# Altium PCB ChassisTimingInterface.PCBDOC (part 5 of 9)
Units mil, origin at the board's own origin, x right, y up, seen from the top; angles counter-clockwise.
Board outline 7007.87 x 4368.85 mil, 10 copper layers (Top Layer, Int1 (GND), Int2 (Sign), Int3 (Sign), Int4 (PWR), Int5 (GND), Int6 (Sign), Int7 (Sign), Int8 (GND), Bottom Layer), stack 54.89 mil thick; 537 components, 525 nets, 2288 pads, 1306 vias.
Unrouted connection lines stored in the file: 373.
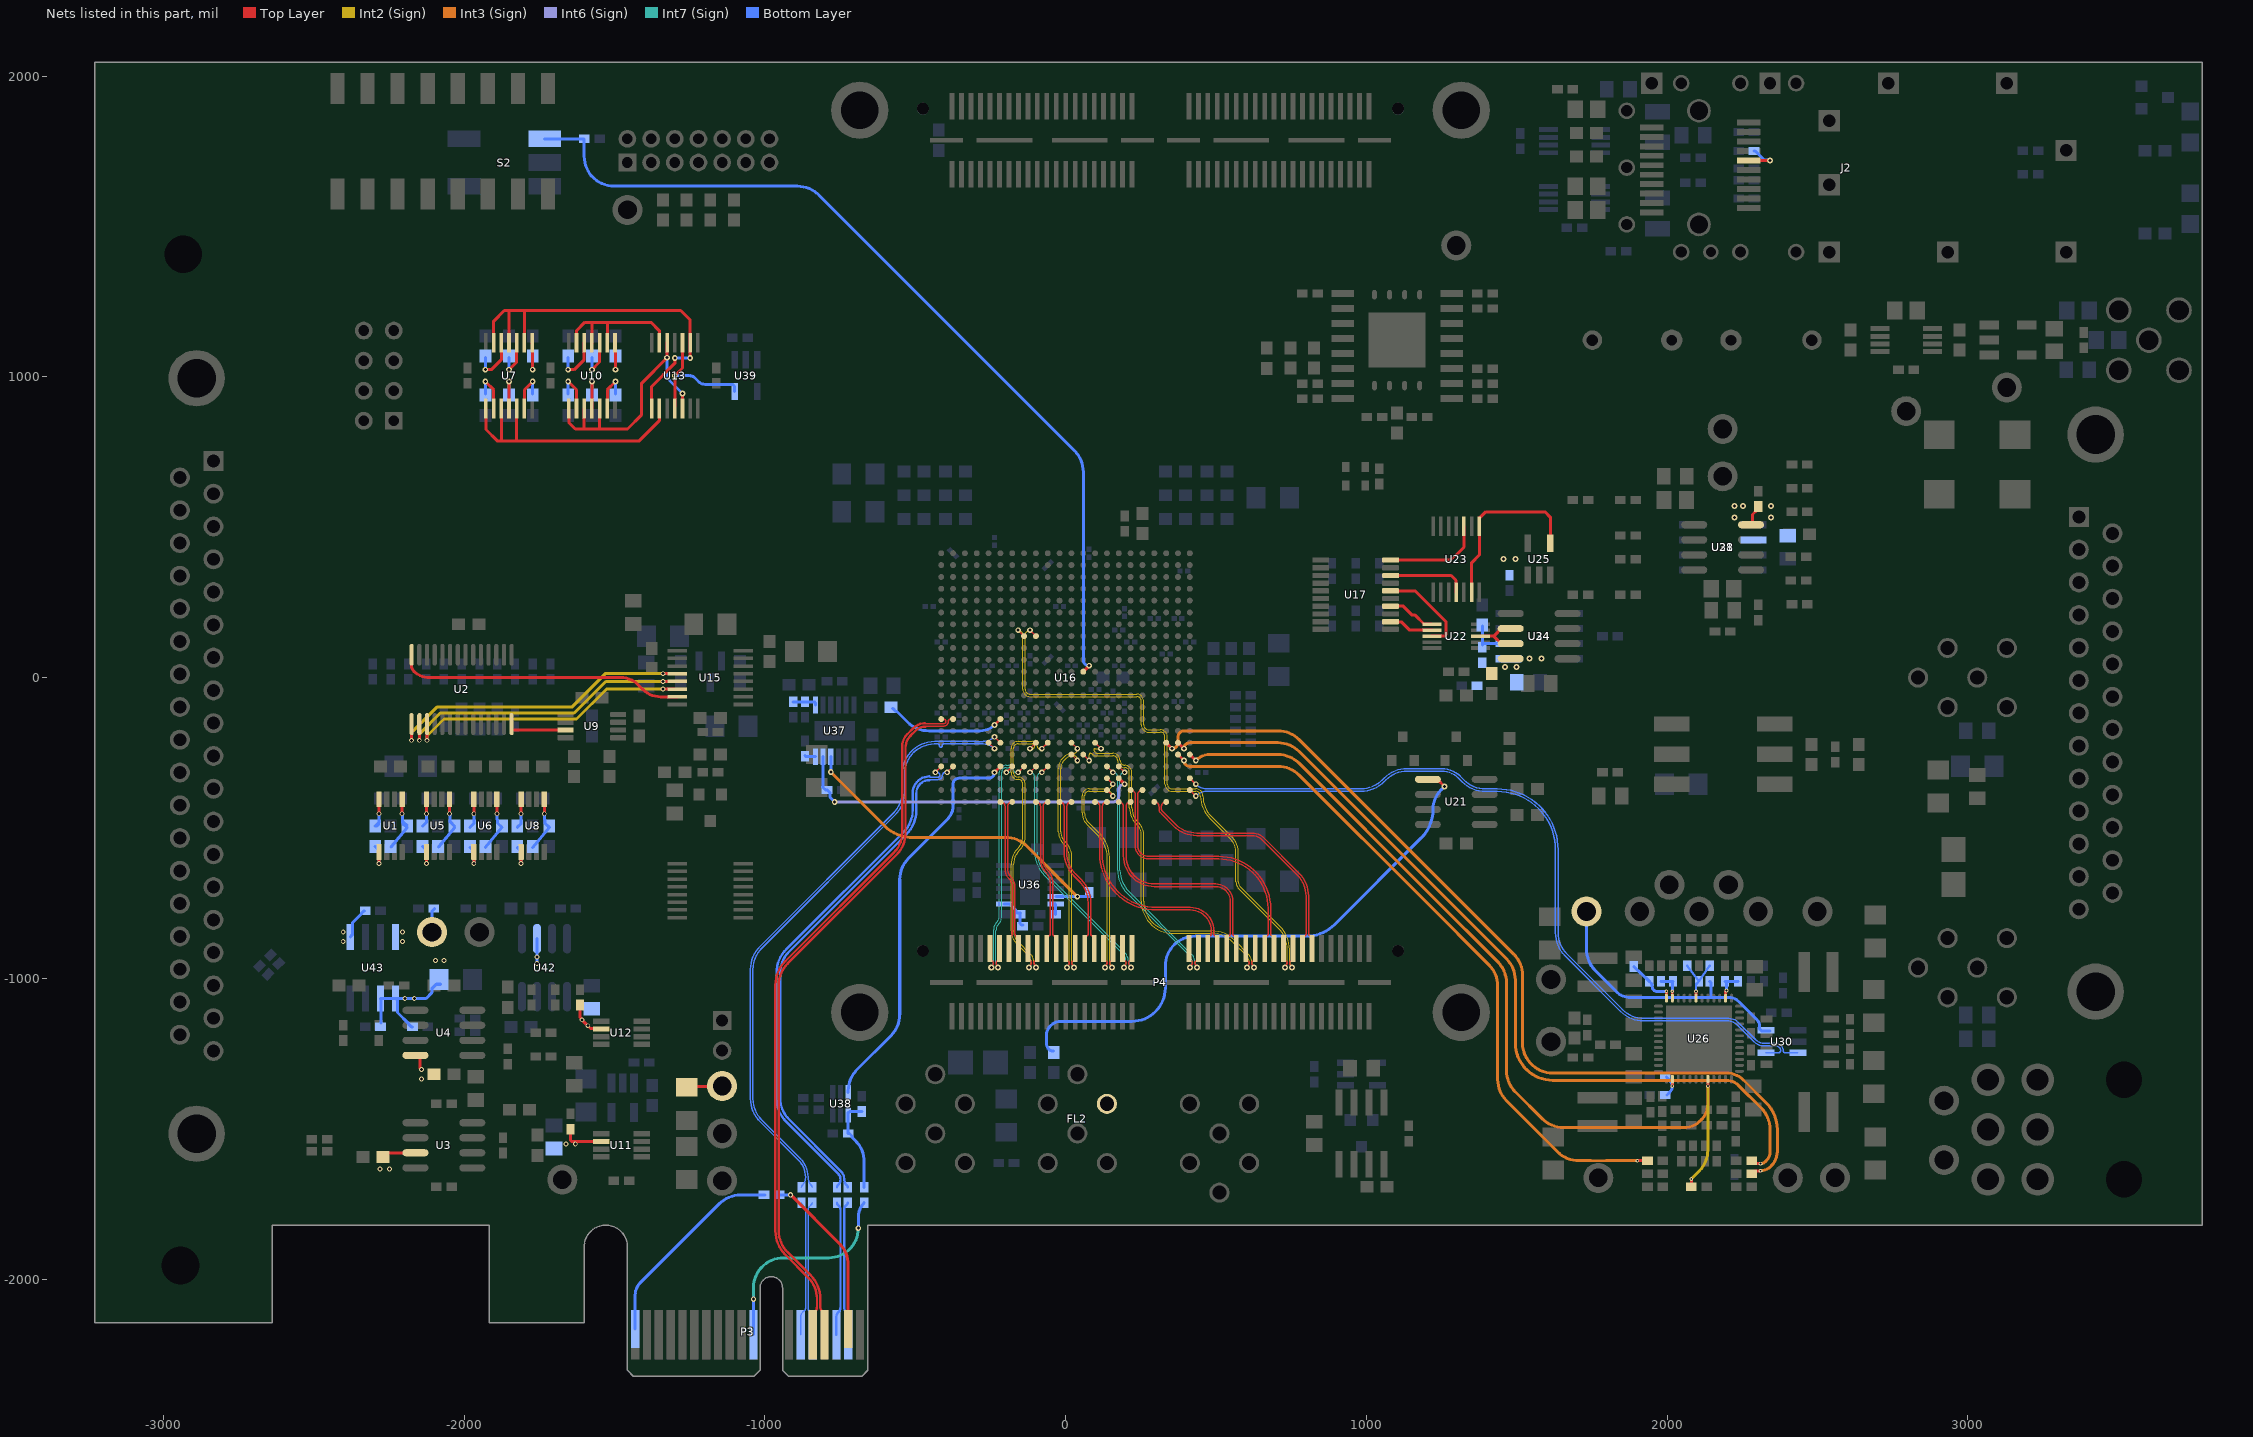
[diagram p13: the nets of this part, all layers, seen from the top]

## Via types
v1: diameter 19, hole 10, Top Layer to Bottom Layer, tented both sides, 667 vias
v2: diameter 20, hole 10, Top Layer to Bottom Layer, tented both sides, 248 vias
v3: diameter 16, hole 10, Top Layer to Bottom Layer, tented both sides, 191 vias
v4: diameter 12, hole 6, Top Layer to Bottom Layer, tented both sides, 85 vias
v5: diameter 19.68, hole 10, Top Layer to Bottom Layer, tented both sides, 50 vias
v6: diameter 17.72, hole 10, Top Layer to Bottom Layer, tented both sides, 19 vias
v7: diameter 19, hole 10, Top Layer to Bottom Layer, 15 vias
v8: diameter 23.62, hole 10, Top Layer to Bottom Layer, tented both sides, 14 vias
v9: diameter 20, hole 10, Top Layer to Bottom Layer, 11 vias
v10: diameter 16, hole 10, Top Layer to Bottom Layer, 3 vias
v11: diameter 22, hole 12, Top Layer to Bottom Layer, tented both sides, 2 vias
v12: diameter 19.02, hole 10, Top Layer to Bottom Layer, tented both sides, 1 vias

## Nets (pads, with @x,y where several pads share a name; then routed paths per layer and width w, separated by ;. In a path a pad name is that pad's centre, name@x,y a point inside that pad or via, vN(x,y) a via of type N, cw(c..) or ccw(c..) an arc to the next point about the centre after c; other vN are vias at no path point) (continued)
NetR116_2: R116.2 R118.1 U26.38 | length 88.4
  Top Layer w10: U26.38@2194.85,-1056.18 2194.85,-1043.99 2197.8,-1041.03 v4(2197.8,-1040.49)
  Bottom Layer w10: R118.1@2192.91,-1009.84 R116.2@2236.22,-1009.84 ; v4(2197.8,-1040.49) R118.1@2197.8,-1012.33
NetR119_1: R119.1 R120.1 R121.1 U26.43 | length 176.8
  Top Layer w10: U26.43@2096.46,-1056.18 v4(2096.46,-1043.3)
  Bottom Layer w8: R121.1@2066.93,-958.66 R120.1@2106.3,-1009.84 ; v4(2096.46,-1043.3) 2096.52,-1043.23 R120.1@2096.52,-1018.62 ; R120.1@2097.52,-1018.62 R120.1@2106.3,-1009.84 ; R119.1@2141.73,-958.66 R120.1@2106.3,-1009.84
NetR122_1: R122.1 R125.2 U26.47 | length 84.5
  Top Layer w9: U26.47@2017.65,-1054.08 v4(2017.65,-1042.94)
  Bottom Layer w10: R125.2@1980.32,-1009.84 R122.1@2019.68,-1009.84 2017.65,-1011.88 v4(2017.65,-1042.94)
NetR123_2: R123.2 R124.1 U26.14 | length 85.3
  Top Layer w10: v4(2017.65,-1358.26) U26.14@2017.68,-1345.39
  Bottom Layer w10: R124.1@1998.03,-1328.74 2006.81,-1337.52 2006.81,-1339.49 2012.04,-1344.72 cw(c1998.5,-1358.26) v4(2017.65,-1358.26) cw(c1988.95,-1358.26) 2009.24,-1378.55 R123.2@2000,-1387.8
NetR126_1: R126.1 R127.2 U26.48 | length 170.9
  Top Layer w9: U26.48@1998.03,-1065.94 v4@1998,-1043.26
  Bottom Layer w10: R127.2@1889.76,-960.63 R126.1@1940.94,-1009.84 1945.15,-1014.04 cw(c1931.63,-1027.56) 1950.74,-1027.56 ccw(c1966.42,-1027.56) 1966.42,-1043.23 v4(1997.97,-1043.23)
NetR128_1: R128.1 R129.1 U34.2 | length 151.5
  Bottom Layer w10: R129.1@1385.83,171.26 1385.83,108.27 1390.35,112.8 U34.2@1472.44,112.8
NetR136_1: R136.1 U36.5 U37.4 | length 1146.7
  Int3 (Sign) w10: v1(-780.51,-313.98) -600.63,-493.86 ccw(c-509.76,-402.98) -536.42,-528.7 ccw(c-509.76,-402.98) -509.76,-531.5 -198.9,-531.5 cw(c-198.9,-631.5) -128.19,-560.79 v1(39.37,-728.35)
  Bottom Layer w10: v1(-780.51,-313.98) U37.4@-780.51,-263.17 ; U36.5@-31.5,-728.35 R136.1@82.68,-728.35
NetR137_2: R137.2 U21.5 | length 1929.5
  Top Layer w10: U21.5@1204.72,-342.52 cw(c1214.23,-352.02) U21.5@1214.23,-338.58 ; U21.5@1204.72,-338.39 1236.12,-338.39 1259.84,-362.11 v2(1259.84,-362.2)
  Bottom Layer w10: R137.2@-39.37,-1242.13 cw(c-39.37,-1218.24) -63.26,-1218.24 -63.26,-1190.71 cw(c-15.39,-1190.71) -15.39,-1142.84 221.26,-1142.84 ccw(c221.26,-1032.41) 331.69,-1032.41 331.69,-959.75 cw(c431.69,-959.75) 431.69,-859.75 801.1,-859.75 ccw(c801.1,-726.77) 895.13,-820.8 1183.01,-532.92 ccw(c1088.98,-438.89) 1221.96,-438.89 cw(c1315.63,-438.89) 1249.39,-372.65 v2(1259.84,-362.2)
NetR138_2: R138.2 U36.6 | length 36.2
  Bottom Layer w10: U36.6@-35.43,-751.97 -33.46,-753.94 R138.2@-33.46,-787.4
NetR139_2: R139.2 R141.1 U36.7 | length 112.4
  Bottom Layer w10: U36.7@-204.11,-752.95 -185.11,-752.95 -164.29,-773.77 -164.29,-778.62 -159.45,-783.46 R141.1@-149.61,-783.46 ; R141.1@-151.57,-787.4 -151.57,-817.99 -146.73,-822.83 R139.2@-141.73,-822.83
NetR145_1: R145.1 U16.F8 | length 398.4
  Top Layer w10: v1(-236.22,-157.48) U16.F8@-216.54,-137.8
  Bottom Layer w10: R145.1@-574.8,-102.36 -564.06,-113.11 -560.12,-113.11 -525.35,-147.88 ccw(c-454.64,-77.17) -454.64,-177.17 -452.76,-177.17 -283.74,-177.17 ccw(c-283.74,-109.96) v1(-236.22,-157.48)
NetR146_2: R146.2 R147.2 R148.1 U38.4 | length 315
  Bottom Layer w10: R147.2@-677.17,-1442.91 -718.58,-1442.91 -722.44,-1446.77 U38.4@-722.44,-1454.72 R148.1@-722.44,-1515.75 -718.5,-1515.75 -709.72,-1524.53 -709.72,-1528.46 -698.58,-1539.61 cw(c-769.29,-1610.32) -669.29,-1610.32 R146.2@-669.29,-1694.88
NetR151_2: R151.2 U37.6 | length 35.8
  Bottom Layer w10: R151.2@-866.14,-259.84 -862.82,-263.17 U37.6@-831.69,-263.17
NetR152_2: R152.2 R153.1 U37.7 | length 82.2
  Bottom Layer w10: R153.1@-905.51,-80.71 R152.2@-866.14,-80.71 -835.19,-80.71 -831.69,-84.21 U37.7@-831.69,-91.17
NetR155_1: R155.1 U10.6 | length 142.3
  Top Layer w10: U10.6@-1523.62,894.69 -1523.62,956.69 v1(-1496.06,984.25)
  Bottom Layer w10: R155.1@-1496.06,942.91 v1(-1496.06,984.25)
NetR156_1: R156.1 U10.8 | length 131.7
  Top Layer w10: U10.8@-1498.03,1113.19 -1497.13,1112.28 -1497.13,1080.97 -1497.05,1080.89 -1497.05,1024.61 v1(-1496.06,1023.62)
  Bottom Layer w10: v1(-1496.06,1023.62) R156.1@-1496.06,1064.96
NetR158_1: R158.1 U10.4 | length 130.9
  Top Layer w10: U10.4@-1574.8,894.69 v1(-1574.8,984.25)
  Bottom Layer w10: R158.1@-1574.8,942.91 v1(-1574.8,984.25)
NetR159_1: R159.1 U10.10 | length 141.5
  Top Layer w10: v1(-1574.8,1023.62) -1549.21,1049.21 U10.10@-1549.21,1113.19
  Bottom Layer w10: v1(-1574.8,1023.62) R159.1@-1574.8,1064.96
NetR161_1: R161.1 U10.2 | length 142.3
  Top Layer w10: v1(-1653.54,984.25) -1625.98,956.69 U10.2@-1625.98,894.69
  Bottom Layer w10: R161.1@-1653.54,942.91 v1(-1653.54,984.25)
NetR162_1: R162.1 U10.12 | length 164.5
  Top Layer w10: v1(-1653.54,1023.62) -1633.86,1023.62 -1600.39,1057.09 U10.12@-1600.39,1113.19
  Bottom Layer w10: v1(-1653.54,1023.62) R162.1@-1653.54,1064.96
NetR164_1: R164.1 R168.2 U8.5 | length 187.1
  Top Layer w10: U8.5@-1733.27,-404.53 -1733.06,-404.74 v3(-1733.06,-452.76)
  Bottom Layer w10: R168.2@-1771.65,-564.96 -1716.54,-498.03 -1731.22,-483.35 -1731.22,-472.58 -1732.22,-471.58 -1732.22,-453.59 v3(-1733.06,-452.76)
NetR165_1: R165.1 U7.6 | length 142.3
  Top Layer w10: U7.6@-1799.21,894.69 -1799.21,956.69 v1(-1771.65,984.25)
  Bottom Layer w10: R165.1@-1771.65,942.91 v1(-1771.65,984.25)
NetR166_1: R166.1 U7.8 | length 131.7
  Top Layer w10: U7.8@-1773.62,1113.19 -1772.72,1112.28 -1772.72,1080.97 -1772.64,1080.89 -1772.64,1024.61 v1(-1771.65,1023.62)
  Bottom Layer w10: v1(-1771.65,1023.62) R166.1@-1771.65,1064.96
NetR170_1: R170.1 U8.8 | length 98.8
  Top Layer w10: v3(-1810.04,-452.76) U8.8@-1810.04,-404.53
  Bottom Layer w10: R170.1@-1822.83,-498.03 -1810.04,-485.24 v3(-1810.04,-452.76)
NetR170_2: R170.2 U8.1 | length 96.8
  Top Layer w10: v3(-1810.04,-618.09) U8.1@-1810.04,-579.72
  Bottom Layer w10: R170.2@-1822.76,-564.96 -1810.04,-577.68 v3(-1810.04,-618.09)
NetR173_1: R173.1 U7.4 | length 130.9
  Top Layer w10: U7.4@-1850.39,894.69 v1(-1850.39,984.25)
  Bottom Layer w10: R173.1@-1850.39,942.91 v1(-1850.39,984.25)
NetR174_1: R174.1 U7.10 | length 141.5
  Top Layer w10: v1(-1850.39,1023.62) -1824.8,1049.21 U7.10@-1824.8,1113.19
  Bottom Layer w10: v1(-1850.39,1023.62) R174.1@-1850.39,1064.96
NetR175_1: R175.1 R180.2 U6.5 | length 187.1
  Top Layer w10: v3(-1890.75,-452.76) U6.5@-1890.75,-404.53
  Bottom Layer w10: R180.2@-1929.13,-564.96 -1874.02,-498.03 -1888.7,-483.35 -1888.7,-472.58 -1889.7,-471.58 -1889.7,-453.8 v3(-1890.75,-452.76)
NetR178_1: R178.1 U7.2 | length 142.3
  Top Layer w10: v1(-1929.13,984.25) -1901.57,956.69 U7.2@-1901.57,894.69
  Bottom Layer w10: R178.1@-1929.13,942.91 v1(-1929.13,984.25)
NetR179_1: R179.1 U7.12 | length 164.5
  Top Layer w10: v1(-1929.13,1023.62) -1909.45,1023.62 -1875.98,1057.09 U7.12@-1875.98,1113.19
  Bottom Layer w10: v1(-1929.13,1023.62) R179.1@-1929.13,1064.96
NetR186_1: R186.1 U6.8 | length 98.8
  Top Layer w10: v3(-1967.52,-452.76) U6.8@-1967.52,-404.53
  Bottom Layer w10: R186.1@-1980.32,-498.03 -1967.52,-485.24 v3(-1967.52,-452.76)
NetR186_2: R186.2 U6.1 | length 96.8
  Top Layer w10: v3(-1967.52,-618.09) U6.1@-1967.52,-579.72
  Bottom Layer w10: R186.2@-1980.24,-564.96 -1967.52,-577.68 v3(-1967.52,-618.09)
NetR189_1: R189.1 R192.2 U5.5 | length 180.2
  Top Layer w10: v3(-2048.23,-452.76) U5.5@-2048.23,-404.53
  Bottom Layer w10: R192.2@-2084.68,-562.61 R189.1@-2031.5,-498.03 ; v3(-2048.23,-452.76) -2047.18,-453.8 -2047.18,-471.58 -2046.18,-472.58 -2046.18,-479.41 R189.1@-2031.5,-494.09
NetR195_1: R195.1 U5.8 | length 94.9
  Top Layer w10: v3(-2125,-452.76) U5.8@-2125,-404.53
  Bottom Layer w10: R195.1@-2137.8,-494.09 -2125,-481.3 v3(-2125,-452.76)
NetR195_2: R195.2 U5.1 | length 103.5
  Top Layer w10: v3@-2125,-620.88 U5.1@-2125,-579.72
  Bottom Layer w10: R195.2@-2137.8,-561.02 -2125,-573.82 v3(-2125,-618.11)
NetR197_1: R197.1 R198.2 U1.5 | length 207
  Top Layer w10: v3(-2205.71,-452.76) U1.5@-2205.71,-404.53 cw(c-2205.71,-405.51) U1.5@-2204.72,-405.51
  Bottom Layer w10: R198.2@-2242.16,-562.61 R197.1@-2188.98,-498.03 ; v3(-2205.71,-452.76) -2204.66,-453.8 -2204.66,-478.28 -2204.72,-478.35 ccw(c-2188.98,-478.35) R197.1@-2188.98,-494.09 -2188.98,-493.09 -2203.66,-478.41 R197.1@-2204.66,-478.41
NetR200_1: R200.1 U1.8 | length 115
  Top Layer w10: U1.8@-2283.46,-405.51 cw(c-2282.48,-405.51) U1.8@-2282.48,-404.53 v3(-2282.48,-452.76)
  Bottom Layer w10: R200.1@-2283.46,-482.28 cw(c-2295.28,-482.28) R200.1@-2295.28,-494.09 -2282.48,-481.3 v3(-2282.48,-452.76)
NetR200_2: R200.2 U1.1 | length 100.7
  Top Layer w10: v3(-2282.48,-618.09) U1.1@-2282.48,-579.72
  Bottom Layer w10: R200.2@-2295.28,-561.02 -2282.48,-573.82 v3(-2282.48,-618.09)
NetU2_14: U2.14 U15.7 | length 958.1
  Top Layer w10: U2.14@-2174.21,75.79 -2174.21,38.39 ccw(c-2150.45,38.39) -2167.25,21.58 ccw(c-2115.15,73.69) -2115.15,0 -1478.29,0 cw(c-1478.29,-80.65) -1421.26,-23.62 -1405.51,-39.37 ccw(c-1346.11,20.03) -1346.11,-63.98 U15.7@-1290.35,-63.98
NetU2_15: U2.15 U15.4 | length 1045.3
  Top Layer w10: v3(-2174.21,-208.66) U2.15@-2174.21,-154.53 ; v3(-1338.58,12.79) U15.4@-1290.35,12.79
  Int2 (Sign) w10: v3(-2174.21,-208.66) -2174.21,-182.09 -2090.55,-98.43 -1641.68,-98.43 -1530.46,12.79 v3(-1338.58,12.79)
NetU2_16: U2.16 U15.5 | length 1005.6
  Top Layer w10: v3(-2148.62,-208.66) U2.16@-2148.62,-154.53 ; v3(-1338.58,-12.8) U15.5@-1290.35,-12.8
  Int2 (Sign) w10: v3(-2148.62,-208.66) -2148.62,-187.99 -2078.74,-118.11 -1633.8,-118.11 -1528.49,-12.8 v3(-1338.58,-12.8)
NetU2_17: U2.17 U15.6 | length 966
  Top Layer w10: v3(-2123.03,-208.66) U2.17@-2123.03,-154.53 ; v3(-1338.58,-38.39) U15.6@-1290.35,-38.39
  Int2 (Sign) w10: v3(-2123.03,-208.66) -2123.03,-193.9 -2066.93,-137.8 -1625.93,-137.8 -1526.52,-38.39 v3(-1338.58,-38.39)
NetU2_28: U2.28 U9.3 | length 193.9
  Top Layer w10: U2.28@-1841.54,-154.53 -1841.54,-172.47 -1839.79,-174.21 U9.3@-1666.34,-174.21
NetU7_1: U7.1 U7.3 U7.5 U13.9 | length 945.6
  Top Layer w10: U7.1@-1927.17,894.69 -1927.17,824.8 -1889.76,787.4 -1875.98,787.4 ; U7.3@-1875.98,894.69 -1875.98,787.4 ; U7.5@-1824.8,894.69 -1824.8,789.37 -1826.77,787.4 ; U13.9@-1350.39,894.69 -1350.39,854.33 -1417.32,787.4 -1826.77,787.4 ; -1875.98,787.4 -1826.77,787.4
NetU7_9: U7.9 U7.11 U7.13 U13.2 U13.8 | length 1345
  Top Layer w10: U7.13@-1901.57,1113.19 -1901.57,1185.04 -1866.14,1220.47 -1850.39,1220.47 ; U7.11@-1850.39,1113.19 -1850.39,1220.47 ; U7.9@-1799.21,1113.19 -1799.21,1220.47 ; U13.8@-1375.98,894.69 -1375.98,968.19 -1299.21,1044.96 v1(-1299.21,1062.79) ; v1(-1248.03,1062.79) U13.2@-1248.03,1113.19 -1248.03,1188.98 -1279.53,1220.47 -1799.21,1220.47 ; -1850.39,1220.47 -1799.21,1220.47
  Bottom Layer w10: v1(-1299.21,1062.79) v1(-1248.03,1062.79)
NetU10_1: U10.1 U10.3 U10.5 U13.5 U13.12 | length 916.4
  Top Layer w10: U10.1@-1651.57,894.69 -1651.57,848.43 -1629.92,826.77 -1547.24,826.77 ; -1600.5,826.99 -1600.39,827.1 U10.3@-1600.39,894.69 ; U10.5@-1549.21,894.69 -1549.21,828.74 -1547.24,826.77 ; U13.5@-1324.8,1113.19 v1(-1324.8,1063.48) -1409.45,978.84 -1409.45,874.02 -1456.69,826.77 -1547.24,826.77 ; U13.12@-1273.62,894.69 v1(-1273.62,944.88)
  Bottom Layer w10: v1(-1324.8,1063.48) -1324.8,1007.94 ccw(c-1296.14,1007.94) -1316.41,987.67 v1(-1273.62,944.88)
NetU10_9: U10.9 U10.11 U10.13 U13.6 | length 515
  Top Layer w10: U10.13@-1625.98,1113.19 -1625.98,1153.54 -1598.43,1181.1 -1574.8,1181.1 ; U10.11@-1574.8,1113.19 -1574.8,1181.1 ; U10.9@-1523.62,1113.19 -1523.62,1181.1 ; U13.6@-1350.39,1113.19 -1350.39,1153.54 -1377.95,1181.1 -1523.62,1181.1 ; -1574.8,1181.1 -1523.62,1181.1
NetU13_3: U13.3 U13.11 U39.5 | length 451
  Top Layer w10: U13.11@-1299.21,901.57 v1(-1299.21,1003.94) -1273.62,1029.53 U13.3@-1273.62,1113.19
  Bottom Layer w10: v1(-1299.21,1003.94) -1251.29,1003.94 cw(c-1251.29,977.05) -1232.3,996.08 -1220.47,984.25 ccw(c-1198.93,1005.79) -1198.93,975.33 -1112.08,975.33 -1111.08,974.33 -1106.22,974.33 -1100.39,968.5 U39.5@-1100.39,950.79
NetU17_12: U17.12 U22.7 | length 149.6
  Top Layer w10: U17.12@1080.71,186.02 1081.38,185.35 1116.52,185.35 1144.39,157.48 U22.7@1218.5,157.48
NetU17_14: U17.14 U22.6 | length 162.7
  Top Layer w10: U17.14@1080.71,237.2 1123.17,237.2 1152.73,207.64 1162.44,207.64 1192.01,178.07 1217.6,178.07 U22.6@1218.5,177.17
NetU17_16: U17.16 U22.8 | length 318.8
  Top Layer w10: U17.16@1080.71,288.39 1162.26,288.39 1265.7,184.94 1265.7,143.65 1259.84,137.8 U22.8@1218.5,137.8
NetU17_18: U17.18 U23.11 | length 256.9
  Top Layer w10: U17.18@1087.6,339.57 1282.48,339.57 1298.61,323.44 1298.61,285.06 U23.11@1299.21,284.45
NetU17_20: U17.20 U23.3 | length 331.2
  Top Layer w10: U17.20@1080.71,390.75 1281.89,390.75 1324.8,433.66 U23.3@1324.8,502.95
NetU22_3: U22.3 U24.6 U24.7 | length 195.5
  Top Layer w10: U22.3@1379.92,137.8 1423.82,137.8 ; U24.7@1488.19,110.24 1451.38,110.24 1423.82,137.8 ; U24.6@1488.19,165.35 1451.38,165.35 1423.82,137.8
NetU23_1: U23.1 U23.13 U25.4 | length 595.8
  Top Layer w10: U23.13@1350.39,283.46 1350.39,381.89 1375.98,407.48 1375.98,529.53 1397.64,551.18 1594.49,551.18 1612.2,533.46 U25.4@1612.2,446.85
P5V: C2.2 C4.2 C14.1 C16.1 C206.1 C209.1 C213.2 C215.2 C218.2 R193.1 TP1.1 U3.7 U4.8 U11.2 U12.2 U42.2 U43.1 U43.2 | length 1020.9
  Top Layer w10: C2.2@-2263.78,-1594.49 -2263.78,-1590.87 -2253.03,-1580.12 U3.7@-2161.42,-1580.12 ; U4.8@-2161.42,-1256.1 -2151.84,-1256.1 -2145.55,-1262.39 -2145.55,-1299.33 v3(-2141.73,-1303.15) ; C14.1@-1645.67,-1501.97 -1645.67,-1539.37 -1642.72,-1542.32 U11.2@-1543.31,-1542.32 ; C16.1@-1614.17,-1101.38 -1614.17,-1130.22 -1608.22,-1136.17 v3(-1608.22,-1137.8) -1579.32,-1166.69 -1544.92,-1166.69 U12.2@-1543.31,-1168.31
  Bottom Layer w10: U43.2@-2278.15,-1066.93 -2276.18,-1068.9 C218.2@-2276.18,-1149.02 ; U43.2@-2275.59,-1066.93 U43.1@-2228.15,-1066.93 ; C215.2@-2171.26,-1161.42 -2175.2,-1161.42 -2183.98,-1152.64 -2183.98,-1150.67 -2221.34,-1113.31 -2221.34,-1073.74 U43.1@-2228.15,-1066.93 ; TP1.1@-2106.3,-846.46 -2106.3,-776.5 R193.1@-2097.52,-767.72 ; C213.2@-2078.74,-1019.68 -2092.22,-1019.68 -2106.91,-1034.37 -2106.91,-1047.85 -2125.98,-1066.93 U43.1@-2228.15,-1066.93 ; v3(-1757.28,-950.41) U42.2@-1757.28,-868.11
  other v3: -2279.53,-1633.86 -2248.03,-1633.86 -1661.42,-1551.18 -1629.92,-1551.18 -2141.73,-1334.65 -1588.54,-1157.48 -2196.85,-1066.93 -2165.35,-1066.93 -2094.49,-940.94 -2066.93,-940.94 -1757.28,-929.57
P10V: C33.2 C64.2 C82.1 C91.1 C93.1 R128.2 R130.1 U24.8 U28.8 U31.2 U34.1 | length 57.2
  Top Layer w10: U28.8@2279.53,508.07 2281.91,508.07 2284.55,510.71 2284.55,542.42 C64.2@2298.23,556.1
  other v2: 1460.63,35.43 1500,35.43 1543.31,62.99 1582.68,62.99 1456.69,393.7 1496.06,393.7 2224.41,531.5 2346.46,531.5 2224.41,570.87 2251.97,570.87 2346.46,570.87
P12V: C21.2 C217.2 FL2.2 TP7.1 U43.5 U43.8 | length 227.2
  Top Layer w10: C21.2@-1259.84,-1362.2 -1257.87,-1360.24 -1143.7,-1360.24 TP7.1@-1141.73,-1358.27
  Bottom Layer w10: U43.5@-2378.15,-862.2 -2371.34,-855.39 -2371.34,-816.22 -2341.46,-786.34 -2341.46,-784.37 -2332.68,-775.59 C217.2@-2330.71,-775.59
  other v3: -2401.57,-877.95 -2204.72,-877.95 -2401.57,-846.46 -2204.72,-846.46
P_SYNC: R119.2 TP11.1 U30.5 | length 930.3
  Bottom Layer w10: TP11.1@1732.28,-777.56 1732.28,-903.2 ccw(c1832.28,-903.2) 1761.57,-973.91 1835.47,-1047.81 ccw(c1872.13,-1011.15) 1872.13,-1062.99 2145.67,-1062.99 ; R119.2@2141.73,-1009.84 2145.67,-1013.78 2145.67,-1062.99 ; U30.5@2342.13,-1175.2 2314.88,-1175.2 2307.09,-1167.4 2307.09,-1156.04 ccw(c2282.06,-1156.04) 2299.77,-1138.35 2238.32,-1076.9 ccw(c2204.72,-1110.52) 2204.72,-1062.99 2145.67,-1062.99
PCIE.PCIE_CLK_N: C198.2 U16.E6 | length 2046.4
  Top Layer w5: U16.E6@-255.91,-216.54 v1(-236.22,-236.22)
  Bottom Layer w5: C198.2@-842.52,-1694.88 ccw(c-852.02,-1694.88) -845.3,-1688.16 cw(c-819.03,-1661.89) -856.19,-1661.89 -856.19,-1661.75 ccw(c-946.15,-1661.75) -882.54,-1598.13 -1010.08,-1470.59 cw(c-939.37,-1399.88) -1039.37,-1399.88 -1039.37,-970.56 cw(c-939.37,-970.56) -1010.08,-899.84 -566.84,-456.6 ccw(c-643.2,-380.24) -535.21,-380.24 -535.21,-320.59 cw(c-435.21,-320.59) -436.86,-220.6 cw(c-435.21,-320.59) -436.48,-220.59 cw(c-435.21,-320.59) -435.21,-220.59 -424.44,-220.59 cw(c-424.44,-225.59) -419.44,-225.59 -419.44,-226.26 ccw(c-414.48,-226.26) -414.48,-231.22 ccw(c-414.48,-226.26) -409.52,-226.26 -409.52,-225.59 cw(c-404.52,-225.59) -404.52,-220.59 -385.34,-220.59 -300,-220.59 -299.95,-220.54 -274.16,-220.54 -274.11,-220.59 -273.97,-220.59 cw(c-273.97,-273.97) v1(-236.22,-236.22)
PCIE.PCIE_CLK_P: C199.2 U16.F6 | length 2046.4
  Top Layer w5: v1(-236.22,-196.85) U16.F6@-216.54,-216.54
  Bottom Layer w5: C199.2@-877.95,-1694.88 cw(c-868.45,-1694.88) -875.17,-1688.16 ccw(c-901.44,-1661.89) -864.29,-1661.89 ccw(c-946.49,-1661.89) -888.36,-1603.76 -1015.83,-1476.3 cw(c-939.44,-1399.91) -1047.47,-1399.91 -1047.47,-970.51 cw(c-939.48,-970.51) -1015.84,-894.15 -572.6,-450.9 ccw(c-643.31,-380.19) -543.31,-380.19 -543.31,-320.59 cw(c-435.21,-320.59) -435.21,-212.49 -373.85,-212.49 -300.15,-212.49 -300,-212.49 -299.95,-212.54 -274.16,-212.54 -274.11,-212.49 -273.97,-212.49 ccw(c-273.97,-159.11) v1(-236.22,-196.85)
PCIE.PCIE_PERST: U16.F4 U38.3 | length 1342.2
  Top Layer w10: v1(-236.22,-314.96) U16.F4@-216.54,-295.28
  Bottom Layer w10: U38.3@-722.44,-1379.92 -722.44,-1374.1 cw(c-622.44,-1374.1) -693.15,-1303.39 -580.47,-1190.71 ccw(c-651.18,-1120) -551.18,-1120 -551.18,-671.34 cw(c-451.18,-671.34) -521.89,-600.63 -393.7,-472.44 ccw(c-441.22,-424.92) -374.02,-424.92 -374.02,-354.27 cw(c-354.39,-354.27) -354.39,-334.65 -255.91,-334.65 ccw(c-255.91,-314.96) v1(-236.22,-314.96)
PCIE.PCIE_PWRGD: R149.1 U16.T3 U37.5 | length 1203.6
  Top Layer w10: U16.T3@177.17,-334.65 v1(196.85,-354.33)
  Int6 (Sign) w10: v1(-767.72,-413.39) -536.42,-413.39 157.48,-413.39 ccw(c157.48,-393.7) 177.17,-393.7 177.17,-374.02 cw(c196.85,-374.02) v1(196.85,-354.33)
  Bottom Layer w10: U37.5@-806.1,-263.17 -806.1,-359.38 -806.02,-359.46 -806.02,-365.24 -797.24,-374.02 -792.24,-374.02 -783.46,-382.8 -783.46,-397.64 v1(-767.72,-413.39)
PCIE.PCIE_RX0_N: P3.B14 U16.A8 | length 2307.7
  Top Layer w5: -467.72,-151.85 -466.12,-153.44 -452.76,-153.44 -405.47,-153.44 ccw(c-405.47,-145.67) -397.7,-145.67 ccw(c-405.57,-145.67) -405.57,-137.8 U16.A8@-413.39,-137.8
  Top Layer w8: P3.B14@-833.48,-2109.07 ccw(c-850.55,-2092.01) -826.42,-2092.01 -826.42,-2065.4 ccw(c-926.42,-2065.4) -855.71,-1994.69 -932.06,-1918.34 cw(c-853.57,-1839.85) -964.57,-1839.85 -964.57,-1021.86 cw(c-853.62,-1021.86) -932.07,-943.41 -569.82,-581.16 ccw(c-634.15,-516.84) -543.18,-516.84 -543.18,-229.33 cw(c-485.09,-229.33) -526.16,-188.25 -505.86,-167.95 cw(c-466.97,-206.84) -469.32,-151.89 cw(c-466.97,-206.84) -467.72,-151.85
PCIE.PCIE_RX0_P: P3.B15 U16.B8 | length 2380.2
  Top Layer w5: -466.92,-162.94 -465.42,-161.44 -452.76,-161.44 -405.47,-161.44 ccw(c-405.47,-145.67) -389.7,-145.67 cw(c-381.83,-145.67) -381.83,-137.8 U16.B8@-374.02,-137.8
  Top Layer w8: P3.B15@-801.18,-2185.04 -801.18,-2126.14 ccw(c-825.31,-2126.14) -808.25,-2109.07 cw(c-791.19,-2092.01) -815.32,-2092.01 -815.32,-2065.26 ccw(c-926.08,-2065.26) -847.76,-1986.94 -924.18,-1910.52 cw(c-853.47,-1839.81) -953.47,-1839.81 -953.47,-1021.93 cw(c-853.47,-1021.93) -924.18,-951.22 -561.93,-588.97 ccw(c-634.01,-516.9) -561.85,-588.89 ccw(c-634.01,-516.9) -532.08,-516.9 -532.08,-233.93 cw(c-473.99,-233.93) -532.08,-233.82 cw(c-473.99,-233.93) -515.14,-192.93 cw(c-473.99,-233.93) -515.06,-192.85 -498.05,-175.84 ; -498.03,-175.82 cw(c-466.92,-206.96) -466.92,-162.94
PCIE.PCIE_TX0_N: C194.2 U16.A4 | length 1750.3
  Top Layer w5: v1(-433.07,-314.96) U16.A4@-413.39,-295.28
  Bottom Layer w5: -452.76,-328.68 -450.72,-330.71 -423.18,-330.71 ccw(c-423.18,-325.01) -417.49,-325.01 ccw(c-427.54,-325.01) -427.54,-314.96 v1(-433.07,-314.96)
  Bottom Layer w8: C194.2@-759.84,-1694.88 cw(c-750.34,-1694.88) -757.06,-1688.16 -756.07,-1687.18 ccw(c-774.94,-1668.31) -748.26,-1668.31 ccw(c-774.94,-1668.31) -756.07,-1649.44 -928.22,-1477.29 cw(c-848.88,-1397.96) -961.08,-1397.96 -961.08,-982.32 cw(c-848.94,-982.32) -928.24,-903.02 -537.62,-512.4 ccw(c-608.33,-441.69) -508.33,-441.69 -508.33,-384.25 cw(c-452.76,-384.25) -452.76,-328.68
PCIE.PCIE_TX0_P: C193.2 U16.B4 | length 1743.9
  Top Layer w5: v1(-393.7,-314.96) U16.B4@-374.02,-295.28
  Bottom Layer w5: -452.76,-340.94 -450.72,-338.91 -423.18,-338.91 ccw(c-423.18,-325.01) -409.29,-325.01 cw(c-399.24,-325.01) -399.24,-314.96 v1(-393.7,-314.96)
  Bottom Layer w8: C193.2@-724.41,-1694.88 ccw(c-733.91,-1694.88) -727.19,-1688.16 cw(c-705.95,-1666.91) -735.99,-1666.91 ccw(c-771.58,-1666.91) -746.42,-1641.75 -919.53,-1468.64 cw(c-848.82,-1397.93) -948.82,-1397.93 -948.82,-982.37 cw(c-848.82,-982.37) -919.53,-911.66 -528.91,-521.03 ccw(c-608.21,-441.74) -496.06,-441.74 -496.06,-384.25 cw(c-452.76,-384.25) -452.76,-340.94
PER0_N: C193.1 P3.A17 | length 446.1
  Bottom Layer w8: C193.1@-724.41,-1746.06 cw(c-733.91,-1746.06) -727.19,-1752.78 -730.2,-1755.79 ccw(c-716.22,-1769.78) -735.99,-1769.78 -735.99,-2093 ccw(c-712.86,-2093) -729.22,-2109.36 cw(c-745.58,-2125.73) -722.44,-2125.73 P3.A17@-722.44,-2185.04
PER0_P: C194.1 P3.A16 | length 446.1
  Bottom Layer w8: P3.A16@-761.81,-2185.04 -761.81,-2125.73 cw(c-738.67,-2125.73) -755.03,-2109.36 ccw(c-771.4,-2093) -748.26,-2093 -748.26,-1769.78 ccw(c-768.03,-1769.78) -754.05,-1755.79 -757.06,-1752.78 cw(c-750.34,-1746.06) C194.1@-759.84,-1746.06
PERST#: P3.A11 R146.1 | length 707.7
  Int7 (Sign) w10: v6(-1037.4,-2066.93) -1037.4,-2029.13 cw(c-937.4,-2029.13) -937.4,-1929.13 -787.01,-1929.13 ccw(c-787.01,-1831.1) -688.98,-1831.1 v6(-688.98,-1830.71)
  Bottom Layer w10: P3.A11@-1037.4,-2185.04 v6(-1037.4,-2066.93) ; v6(-688.98,-1830.71) -688.98,-1793.59 cw(c-621.77,-1793.59) R146.1@-669.32,-1746.09
POWER.PWRGOOD: R72.1 U16.AB5 U26.20 | length 2920.1
  Top Layer w10: U16.AB5@413.39,-255.91 v1(433.07,-275.59) ; R72.1@2080.71,-1692.91 v4(2080.71,-1667.32) ; v4(2135.83,-1358.26) U26.20@2135.83,-1345.39
  Int3 (Sign) w10: v1(433.07,-275.59) cw(c480.6,-323.12) 480.6,-255.91 536.42,-255.91 706.61,-255.91 cw(c706.61,-355.91) 777.32,-285.19 1220.47,-728.35 1437.01,-944.88 cw(c1366.3,-1015.59) 1466.3,-1015.59 1466.3,-1306.77 ccw(c1566.3,-1306.77) 1495.59,-1377.48 ; 1496.06,-1377.95 1584.88,-1466.77 ccw(c1655.59,-1396.06) 1655.59,-1496.06 2055.51,-1496.06 ccw(c2055.51,-1415.75) 2135.83,-1415.75 v4(2135.83,-1358.26)
  Int2 (Sign) w10: v4(2080.71,-1667.32) 2106.54,-1641.5 ccw(c2035.83,-1570.78) 2135.83,-1570.78 v4(2135.83,-1358.26)
POWER.PWRINT: R63.1 U16.AA5 | length 2336.9
  Top Layer w10: U16.AA5@374.02,-255.91 v1(393.7,-275.59) ; v4(1901.57,-1606.3) R63.1@1935.04,-1606.3
  Int3 (Sign) w8.17: 1746.72,-1606.3 1796.59,-1606.3
  Int3 (Sign) w10: v1(393.7,-275.59) ccw(c413.39,-275.59) 413.39,-295.28 536.42,-295.28 706.61,-295.28 cw(c706.61,-395.28) 777.32,-324.56 1200.79,-748.03 1407.72,-954.96 cw(c1337.01,-1025.67) 1437.01,-1025.67 1437.01,-1336.53 ccw(c1537.01,-1336.53) 1466.3,-1407.24 1636.07,-1577.01 ccw(c1706.78,-1506.3) 1706.78,-1606.3 1746.72,-1606.3 ; 1796.59,-1606.3 v4(1901.57,-1606.3)
POWER.PWRSCL: R85.1 U16.AA6 | length 2859.2
  Top Layer w10: U16.AA6@374.02,-216.54 v1(393.7,-236.22) ; R85.1@2281.5,-1606.3 2290.28,-1615.08 2299.07,-1615.08 2300.07,-1616.08 2310.96,-1616.08 v4(2311.02,-1616.14)
  Int3 (Sign) w10: v1(393.7,-236.22) cw(c413.39,-236.22) 413.39,-216.54 536.42,-216.54 706.61,-216.54 cw(c706.61,-316.54) 777.32,-245.82 1466.3,-934.8 cw(c1395.59,-1005.51) 1495.59,-1005.51 1495.59,-1214.96 ccw(c1619.68,-1214.96) 1619.68,-1339.06 2197.8,-1339.06 cw(c2197.8,-1394.94) 2237.32,-1355.43 2313.23,-1431.34 cw(c2242.52,-1502.05) 2342.52,-1502.05 2342.52,-1576.73 cw(c2300.7,-1576.73) 2330.28,-1606.29 2327.08,-1609.49 cw(c2311.02,-1593.44) v4(2311.02,-1616.14)
POWER.PWRSDA: R84.1 U16.Y6 | length 3016.1
  Top Layer w10: U16.Y6@334.65,-216.54 v1(354.33,-236.22) ; R84.1@2281.5,-1649.61 2290.28,-1640.83 2299.07,-1640.83 2300.07,-1639.83 2310.96,-1639.83 v4(2311.02,-1639.76)
  Int3 (Sign) w10: v1(354.33,-236.22) ccw(c354.33,-216.54) 374.02,-216.54 374.02,-196.85 cw(c393.7,-196.85) 393.7,-177.17 536.42,-177.17 706.61,-177.17 cw(c706.61,-277.17) 777.32,-206.46 1490.4,-919.53 cw(c1419.68,-990.24) 1519.68,-990.24 1519.68,-1214.96 ccw(c1619.68,-1214.96) 1619.68,-1314.96 2197.8,-1314.96 cw(c2197.8,-1394.94) 2254.36,-1338.39 2330.27,-1414.3 cw(c2242.52,-1502.05) 2366.62,-1502.05 2366.62,-1575.58 cw(c2299.55,-1575.58) 2346.97,-1623 2343.78,-1626.19 cw(c2311.02,-1593.44) v4(2311.02,-1639.76)
POWER.PWRSYNC_N: U16.AB2 U30.4 | length 2633.4
  Top Layer w5: U16.AB2@413.39,-374.02 v1(433.07,-393.7)
  Bottom Layer w5: v1(433.07,-393.7) cw(c470.21,-430.84) 470.21,-378.32 982.68,-378.32 ccw(c982.68,-270.01) 1059.27,-346.59 1065.55,-340.31 cw(c1136.26,-411.02) 1136.26,-311.02 1250.06,-311.02 cw(c1250.06,-391.67) 1307.09,-334.65 1319.34,-346.9 ccw(c1396.06,-270.19) 1396.06,-378.68 1435.91,-378.68 cw(c1435.91,-571.96) 1629.2,-571.96 1629.2,-848.39 ccw(c1737.68,-848.39) 1660.97,-925.1 1845.83,-1109.96 ccw(c1922.54,-1033.24) 1922.54,-1141.73 2204.72,-1141.73 cw(c2204.72,-1178.9) 2231.01,-1152.62 2288.7,-1210.31 ccw(c2322.74,-1176.28) 2322.74,-1224.41 2361.84,-1224.41 cw(c2361.84,-1240.16) 2377.59,-1240.16 cw(c2369.72,-1240.16) 2369.72,-1248.03 U30.4@2328.74,-1248.03
POWER.PWRSYNC_P: U16.AB3 U30.3 | length 2646.9
  Top Layer w5: U16.AB3@413.39,-334.65 v1(433.07,-354.33)
  Bottom Layer w5: v1(433.07,-354.33) ccw(c470.21,-317.19) 470.21,-369.72 982.56,-369.72 ccw(c982.56,-269.72) 1053.27,-340.43 1059.55,-334.15 cw(c1136.14,-410.74) 1136.14,-302.42 1250.24,-302.42 cw(c1250.24,-391.24) 1313.04,-328.44 1325.39,-340.79 ccw(c1396.1,-270.08) 1396.1,-370.08 1435.91,-370.08 cw(c1435.91,-571.96) 1637.8,-571.96 1637.8,-848.34 ccw(c1737.8,-848.34) 1667.08,-919.05 1851.87,-1103.84 ccw(c1922.59,-1033.13) 1922.59,-1133.13 2204.75,-1133.13 cw(c2204.75,-1178.85) 2237.07,-1146.52 2294.71,-1204.16 ccw(c2322.83,-1176.04) 2322.83,-1215.81 2361.84,-1215.81 cw(c2361.84,-1240.16) 2386.19,-1240.16 ccw(c2394.06,-1240.16) 2394.06,-1248.03 U30.3@2435.04,-1248.03
PROG: R157.1 S2.1 U16.N12 | length 2998.7
  Top Layer w10: U16.N12@59.06,19.69 v1(78.74,39.37)
  Bottom Layer w10: S2.1@-1732.28,1791.34 R157.1@-1600.39,1791.34 -1600.39,1733.86 ccw(c-1500.39,1733.86) -1500.39,1633.86 -890.88,1633.86 cw(c-890.88,1533.86) -820.17,1604.57 29.77,754.63 cw(c-40.94,683.92) 59.06,683.92 59.06,452.76 59.06,59.06 ccw(c78.74,59.06) v1(78.74,39.37)
PRSNT1#: P3.A1 R154.2 | length 688.1
  Bottom Layer w10: P3.A1@-1431.1,-2165.35 -1431.1,-2054.23 cw(c-1371.45,-2054.23) -1413.64,-2012.05 -1151.34,-1749.76 cw(c-1080.63,-1820.47) -1080.63,-1720.47 R154.2@-1000,-1720.47
PRSNT2#: P3.B17 R154.1 | length 557.8
  Top Layer w10: v6(-914.47,-1719.98) -913.88,-1719.98 -751.73,-1882.13 cw(c-822.44,-1952.84) -722.44,-1952.84 P3.B17@-722.44,-2165.35
  Bottom Layer w10: R154.1@-951.28,-1719.98 v6(-914.47,-1719.98)
RDY: J2.6 R113.1 | length 137.1
  Top Layer w10: J2.6@2271.65,1719.29 v1(2342.52,1719.29)
  Bottom Layer w10: R113.1@2289.37,1750.79 2293.31,1750.79 2322.7,1721.4 2337.98,1721.4 2340.08,1719.29 v1(2342.52,1719.29)
REFCLK_N: C198.1 P3.A14 | length 448.8
  Bottom Layer w5: C198.1@-842.52,-1746.06 cw(c-852.02,-1746.06) -845.3,-1752.78 -849.23,-1756.71 ccw(c-833.03,-1772.9) -855.94,-1772.9 -855.94,-2097.9 ccw(c-846.3,-2097.9) -853.12,-2104.71 ccw(c-852.15,-2103.74) -852.15,-2105.11 cw(c-852.15,-2106.48) -851.18,-2105.51 -846.06,-2110.63 cw(c-859.38,-2123.94) -840.55,-2123.94 P3.A14@-840.55,-2185.04
REFCLK_P: C199.1 P3.A13 | length 448.8
  Bottom Layer w5: P3.A13@-879.92,-2185.04 -879.92,-2123.94 cw(c-861.09,-2123.94) -874.41,-2110.63 -869.29,-2105.51 cw(c-868.32,-2106.48) -868.32,-2105.11 ccw(c-868.32,-2103.74) -867.36,-2104.71 ccw(c-874.17,-2097.9) -864.54,-2097.9 -864.54,-1772.9 ccw(c-887.44,-1772.9) -871.24,-1756.71 -875.17,-1752.78 cw(c-868.45,-1746.06) C199.1@-877.95,-1746.06
S1_16.S1_N: P4.12 U16.G4 | length 821.2
  Top Layer w5: v2(-223.92,-964.57) ccw(c-231.82,-964.57) -226.22,-958.99 -227.52,-957.69 cw(c-218.83,-949) -231.12,-949 -231.12,-948.64 cw(c-223.71,-948.64) -228.95,-943.41 cw(c-226.41,-945.95) -226.41,-942.35 ccw(c-226.41,-938.76) -223.87,-941.31 -222.29,-939.73 ccw(c-228.63,-933.39) -219.67,-933.39 P4.12@-219.67,-900.6 ; v1(-196.85,-314.96) U16.G4@-177.17,-295.28
  Int7 (Sign) w3: v2(-223.92,-964.57) ccw(c-230.58,-964.57) -225.87,-959.86 cw(c-212.47,-946.46) -231.42,-946.46 -231.42,-841.68 cw(c-199.29,-841.68) -222.01,-818.96 ccw(c-244.73,-796.24) -212.6,-796.24 -212.6,-314.96 cw(c-196.85,-314.96) -196.85,-299.21 -189.04,-299.21 cw(c-189.04,-307.09) -181.17,-307.09 cw(c-189.04,-307.09) -189.04,-314.96 v1(-196.85,-314.96)
S1_16.S1_P: P4.10 U16.H4 | length 846.3
  Top Layer w5: P4.10@-251.17,-900.6 -251.17,-933.39 ccw(c-242.21,-933.39) -248.55,-939.72 -246.97,-941.3 ccw(c-244.43,-938.76) -244.43,-942.35 cw(c-244.43,-945.95) -241.89,-943.41 cw(c-247.12,-948.64) -239.72,-948.64 -239.72,-949 cw(c-252.01,-949) -243.32,-957.69 -244.6,-958.98 ccw(c-239.02,-964.57) v2(-246.92,-964.57) ; v1(-157.48,-314.96) U16.H4@-137.8,-295.28
  Int7 (Sign) w3: v2(-246.92,-964.57) cw(c-240.26,-964.57) -244.97,-959.86 ccw(c-258.37,-946.46) -239.42,-946.46 -239.42,-838.36 cw(c-207.29,-838.36) -230.01,-815.65 ccw(c-252.73,-792.93) -220.6,-792.93 -220.6,-314.96 cw(c-196.85,-314.96) -196.85,-291.21 -189.04,-291.21 cw(c-189.04,-307.09) -173.17,-307.09 ccw(c-165.29,-307.09) -165.29,-314.96 v1(-157.48,-314.96)
S1_16.S2_N: P4.14 U16.F1 | length 508
  Top Layer w5: U16.F1@-216.54,-413.39 cw(c-216.54,-428.77) -201.15,-428.77 -201.15,-452.76 -201.15,-637.17 ccw(c-156.82,-637.17) -188.17,-668.52 -188.11,-668.58 cw(c-215.57,-696.04) -176.74,-696.04 -176.74,-852.56 cw(c-184.14,-852.56) -178.9,-857.8 cw(c-181.45,-855.26) -181.45,-858.85 ccw(c-181.45,-862.45) -183.98,-859.9 -185.56,-861.48 ccw(c-179.22,-867.81) -188.19,-867.81 P4.14@-188.19,-900.6
S1_16.S2_P: P4.16 U16.G1 | length 508
  Top Layer w5: U16.G1@-177.17,-413.39 ccw(c-177.17,-428.77) -192.55,-428.77 -192.55,-452.76 -192.55,-637.1 ccw(c-156.62,-637.1) -182.03,-662.5 -181.98,-662.54 cw(c-215.41,-695.97) -168.14,-695.97 -168.14,-852.56 ccw(c-160.73,-852.56) -165.97,-857.8 ccw(c-163.42,-855.26) -163.42,-858.85 cw(c-163.42,-862.45) -160.89,-859.9 -159.3,-861.48 cw(c-165.65,-867.81) -156.69,-867.81 P4.16@-156.69,-900.6
S1_16.S3_N: P4.20 U16.J6 | length 991.8
  Top Layer w5: v1(-118.11,-236.22) U16.J6@-98.43,-216.54 ; v2(-97.94,-964.57) ccw(c-105.83,-964.57) -100.24,-958.99 -101.54,-957.69 cw(c-92.84,-949) -105.14,-949 -105.14,-948.64 cw(c-97.73,-948.64) -102.97,-943.41 cw(c-100.42,-945.95) -100.42,-942.35 ccw(c-100.42,-938.76) -97.89,-941.31 -96.31,-939.73 ccw(c-102.65,-933.39) -93.68,-933.39 P4.20@-93.69,-900.6
  Int2 (Sign) w3: v1(-118.11,-236.22) -110.3,-236.22 ccw(c-110.3,-228.35) -102.43,-228.35 ccw(c-110.3,-228.35) -110.3,-220.47 -157.48,-220.47 ccw(c-157.48,-236.22) -173.23,-236.22 -173.23,-314.96 ccw(c-157.48,-314.96) -157.48,-330.71 -157.35,-330.71 cw(c-157.35,-354.33) -133.73,-354.33 -133.73,-527.16 cw(c-200.92,-527.16) -153.41,-574.67 -153.54,-574.8 ccw(c-106.32,-622.02) -173.1,-622.02 -173.1,-838.46 -173.23,-838.58 -173.23,-842.52 ccw(c-124.5,-842.52) -158.96,-876.97 -116.7,-919.23 cw(c-143.89,-946.43) -105.44,-946.43 ccw(c-86.49,-946.46) -99.88,-959.86 cw(c-104.59,-964.57) v2(-97.94,-964.57)
S1_16.S3_P: P4.18 U16.K6 | length 1016.9
  Top Layer w5: P4.18@-125.19,-900.6 -125.19,-933.39 ccw(c-116.22,-933.39) -122.57,-939.72 -120.99,-941.3 ccw(c-118.45,-938.76) -118.45,-942.35 cw(c-118.45,-945.95) -115.9,-943.41 cw(c-121.14,-948.64) -113.74,-948.64 -113.74,-949 cw(c-126.03,-949) -117.34,-957.69 -118.62,-958.98 ccw(c-113.04,-964.57) v2(-120.94,-964.57) ; v1(-78.74,-236.22) U16.K6@-59.06,-216.54
  Int2 (Sign) w3: v2(-120.94,-964.57) cw(c-114.28,-964.57) -118.99,-959.86 ccw(c-132.38,-946.46) -113.44,-946.46 ccw(c-143.98,-946.46) -122.38,-924.86 -164.63,-882.61 cw(c-124.56,-842.54) -181.23,-842.54 -181.23,-834.65 -181.1,-834.52 -181.1,-621.86 cw(c-106.73,-621.86) -159.32,-569.27 -159.2,-569.15 ccw(c-201.37,-526.98) -141.73,-526.98 -141.73,-354.33 ccw(c-157.35,-354.33) -157.35,-338.71 -157.48,-338.71 cw(c-157.48,-314.96) -181.23,-314.96 -181.23,-236.22 cw(c-157.48,-236.22) -157.48,-212.47 -110.3,-212.47 cw(c-110.3,-228.35) -94.43,-228.35 ccw(c-86.55,-228.35) -86.55,-236.22 v1(-78.74,-236.22)
S1_16.S4_N: P4.22 U16.J1 | length 510.1
  Top Layer w5: U16.J1@-98.43,-413.39 cw(c-98.43,-428.77) -83.04,-428.77 -83.04,-452.76 -83.04,-608.29 ccw(c-32.75,-608.29) -68.31,-643.85 ; -68.28,-643.88 cw(c-110.61,-686.2) -50.75,-686.2 -50.75,-852.56 cw(c-58.16,-852.56) -52.92,-857.8 cw(c-55.46,-855.26) -55.46,-858.85 ccw(c-55.46,-862.45) -58,-859.9 -59.58,-861.48 ccw(c-53.24,-867.81) -62.2,-867.81 P4.22@-62.2,-900.6
S1_16.S4_P: P4.24 U16.K1 | length 510.1
  Top Layer w5: U16.K1@-59.06,-413.39 ccw(c-59.06,-428.77) -74.44,-428.77 -74.44,-452.76 -74.44,-608.25 ccw(c-32.66,-608.25) -62.2,-637.8 -62.09,-637.9 cw(c-110.23,-686.05) -42.15,-686.05 -42.15,-852.56 ccw(c-34.75,-852.56) -39.98,-857.8 ccw(c-37.44,-855.26) -37.44,-858.85 cw(c-37.44,-862.45) -34.91,-859.9 -33.32,-861.48 cw(c-39.66,-867.81) -30.7,-867.81 P4.24@-30.7,-900.6
S1_16.S5_N: P4.28 U16.M5 | length 858.4
  Top Layer w5: U16.M5@19.69,-255.91 v1(39.37,-275.59) ; v2@26.1,-959.86 26.1,-959.35 23.47,-956.72 cw(c29.81,-950.38) 20.85,-950.38 20.85,-948.64 cw(c28.25,-948.64) 23.02,-943.41 cw(c25.56,-945.95) 25.56,-942.35 ccw(c25.56,-938.76) 28.09,-941.31 29.67,-939.73 ccw(c23.34,-933.39) 32.3,-933.39 P4.28@32.3,-900.6
  Int2 (Sign) w3: v2(28.05,-964.57) ccw(c21.39,-964.57) 26.1,-959.86 cw(c39.5,-946.46) 20.55,-946.46 20.55,-594.91 ccw(c-43.71,-594.91) 1.73,-549.47 -1.48,-546.26 cw(c32.98,-511.81) -15.75,-511.81 -15.75,-303.21 cw(c27.56,-303.21) 27.56,-259.91 cw(c27.56,-271.72) 39.37,-271.72 v1(39.37,-275.59)
S1_16.S5_P: P4.26 U16.M6 | length 876
  Top Layer w5: P4.26@0.8,-900.6 0.8,-933.39 ccw(c9.76,-933.39) 3.42,-939.72 5,-941.3 ccw(c7.54,-938.76) 7.54,-942.35 cw(c7.54,-945.95) 10.08,-943.41 cw(c4.84,-948.64) 12.25,-948.64 12.25,-949 cw(c-0.04,-949) 8.65,-957.69 7.36,-958.98 ccw(c12.95,-964.57) v2(5.05,-964.57) ; U16.M6@19.69,-216.54 v1(39.37,-236.22)
  Int2 (Sign) w3: v2(5.05,-964.57) cw(c11.71,-964.57) 7,-959.86 ccw(c-6.4,-946.46) 12.55,-946.46 12.55,-594.92 ccw(c-43.74,-594.92) -3.94,-555.12 -7.15,-551.9 cw(c32.92,-511.83) -23.75,-511.83 -23.75,-303.21 cw(c27.56,-303.21) 27.56,-251.91 ccw(c27.56,-240.09) 39.37,-240.09 v1(39.37,-236.22)
S1_16.S6_N: P4.30 U16.L1 | length 525.5
  Top Layer w5: U16.L1@-19.69,-413.39 cw(c-19.69,-428.77) -4.3,-428.77 -4.3,-452.76 -4.3,-582.5 ccw(c103.27,-582.5) 27.21,-658.57 45.94,-677.3 cw(c-24.77,-748.01) 75.23,-748.01 75.23,-852.56 cw(c67.83,-852.56) 73.06,-857.8 cw(c70.52,-855.26) 70.52,-858.85 ccw(c70.52,-862.45) 67.98,-859.9 66.41,-861.48 ccw(c72.74,-867.81) 63.78,-867.81 P4.30@63.78,-900.6
S1_16.S6_P: P4.32 U16.M1 | length 525.5
  Top Layer w5: U16.M1@19.69,-413.39 ccw(c19.69,-428.77) 4.3,-428.77 4.3,-452.76 4.3,-582.41 ccw(c103.49,-582.41) 33.35,-652.55 52.14,-671.34 cw(c-24.35,-747.84) 83.83,-747.84 83.83,-852.56 ccw(c91.24,-852.56) 86,-857.8 ccw(c88.54,-855.26) 88.54,-858.85 cw(c88.54,-862.45) 91.08,-859.9 92.66,-861.48 cw(c86.32,-867.81) 95.28,-867.81 P4.32@95.28,-900.6
S1_16.S7_N: P4.36 U16.R2 | length 807.5
  Top Layer w5: U16.R2@137.8,-374.02 v1(157.48,-393.7) ; v2@152.08,-959.86 152.08,-959.35 149.46,-956.72 cw(c155.79,-950.38) 146.83,-950.38 146.83,-948.64 cw(c154.24,-948.64) 149,-943.41 cw(c151.54,-945.95) 151.54,-942.35 ccw(c151.54,-938.76) 154.08,-941.31 155.66,-939.73 ccw(c149.32,-933.39) 158.28,-933.39 P4.36@158.28,-900.6
  Int2 (Sign) w3: v2(154.03,-964.57) ccw(c147.37,-964.57) 152.08,-959.86 cw(c165.48,-946.46) 146.53,-946.46 146.53,-597.18 ccw(c38.77,-597.18) 114.97,-520.98 77.26,-483.27 cw(c111.72,-448.82) 62.99,-448.82 62.99,-393.7 cw(c78.68,-393.7) 78.68,-378.02 141.8,-378.02 cw(c141.8,-393.7) v1(157.48,-393.7)
S1_16.S7_P: P4.34 U16.R3 | length 825.1
  Top Layer w5: P4.34@126.78,-900.6 126.78,-933.39 ccw(c135.74,-933.39) 129.4,-939.72 130.98,-941.3 ccw(c133.52,-938.76) 133.52,-942.35 cw(c133.52,-945.95) 136.06,-943.41 cw(c130.83,-948.64) 138.23,-948.64 138.23,-949 cw(c125.94,-949) 134.63,-957.69 133.35,-958.98 ccw(c138.93,-964.57) v2(131.03,-964.57) ; U16.R3@137.8,-334.65 v1(157.48,-354.33)
  Int2 (Sign) w3: v2(131.03,-964.57) cw(c137.69,-964.57) 132.98,-959.86 ccw(c119.58,-946.46) 138.53,-946.46 138.53,-597.28 ccw(c38.53,-597.28) 109.24,-526.56 71.57,-488.89 cw(c111.59,-448.87) 54.99,-448.87 54.99,-393.7 cw(c78.68,-393.7) 78.68,-370.02 141.8,-370.02 ccw(c141.8,-354.33) v1(157.48,-354.33)
S1_16.S8_N: P4.38 U16.J4 | length 879.4
  Top Layer w5: v1(-118.11,-314.96) U16.J4@-98.43,-295.28 ; P4.38@189.76,-900.6 189.76,-933.39 ccw(c198.73,-933.39) 192.38,-939.72 193.96,-941.3 ccw(c196.5,-938.76) 196.5,-942.35 cw(c196.5,-945.95) 199.05,-943.41 cw(c193.81,-948.64) 201.21,-948.64 201.21,-949 cw(c188.92,-949) 197.61,-957.69 196.33,-958.98 ccw(c201.91,-964.57) v2(194.01,-964.57)
  Int7 (Sign) w3: v1(-118.11,-314.96) cw(c-118.11,-330.65) -102.43,-330.65 -102.43,-580.71 ccw(c5.52,-580.71) -70.81,-657.04 189.43,-917.27 cw(c160.24,-946.46) 201.51,-946.46 cw(c182.57,-946.46) 195.96,-959.86 ccw(c200.67,-964.57) v2(194.01,-964.57)
S1_16.S8_P: P4.40 U16.K4 | length 879.5
  Top Layer w5: v1(-78.74,-314.96) U16.K4@-59.06,-295.28 ; v2(217.01,-964.57) ccw(c209.12,-964.57) 214.71,-958.99 213.41,-957.69 cw(c222.11,-949) 209.81,-949 209.81,-948.64 cw(c217.22,-948.64) 211.98,-943.41 cw(c214.53,-945.95) 214.53,-942.35 ccw(c214.53,-938.76) 217.06,-941.31 218.64,-939.73 ccw(c212.3,-933.39) 221.27,-933.39 P4.40@221.26,-900.6
  Int7 (Sign) w3: v1(-78.74,-314.96) ccw(c-78.74,-330.65) -94.43,-330.65 -94.43,-580.69 ccw(c5.57,-580.69) -65.14,-651.4 195.15,-911.68 cw(c160.47,-946.37) 209.51,-946.37 209.51,-946.46 ccw(c228.46,-946.46) 215.07,-959.86 cw(c210.36,-964.57) v2(217.01,-964.57)
S1_16.S9_N: P4.44 U16.T4 | length 857.1
  Top Layer w5: U16.T4@177.17,-295.28 v1(196.85,-314.96) ; v2(437.48,-964.57) ccw(c429.58,-964.57) 435.18,-958.99 433.88,-957.69 cw(c442.57,-949) 430.28,-949 430.28,-948.64 cw(c437.69,-948.64) 432.45,-943.41 cw(c434.99,-945.95) 434.99,-942.35 ccw(c434.99,-938.76) 437.53,-941.31 439.11,-939.73 ccw(c432.77,-933.39) 441.73,-933.39 P4.44@441.73,-900.6
  Int7 (Sign) w3: v1(196.85,-314.96) ccw(c196.85,-330.65) 181.17,-330.65 181.17,-640.24 ccw(c281.17,-640.24) 210.46,-710.95 418.71,-919.2 cw(c391.48,-946.43) 429.98,-946.43 ccw(c448.93,-946.46) 435.53,-959.86 cw(c430.82,-964.57) v2(437.48,-964.57)
S1_16.S9_P: P4.42 U16.R4 | length 857.1
  Top Layer w5: U16.R4@137.8,-295.28 v1(157.48,-314.96) ; P4.42@410.23,-900.6 410.23,-933.39 ccw(c419.19,-933.39) 412.85,-939.72 414.43,-941.3 ccw(c416.97,-938.76) 416.97,-942.35 cw(c416.97,-945.95) 419.51,-943.41 cw(c414.28,-948.64) 421.68,-948.64 421.68,-949 cw(c409.39,-949) 418.08,-957.69 416.8,-958.98 ccw(c422.38,-964.57) v2(414.48,-964.57)
  Int7 (Sign) w3: v1(157.48,-314.96) cw(c157.48,-330.65) 173.17,-330.65 173.17,-640.27 ccw(c281.11,-640.27) 204.78,-716.59 413.02,-924.83 cw(c391.4,-946.46) 421.98,-946.46 cw(c403.03,-946.46) 416.43,-959.86 ccw(c421.14,-964.57) v2(414.48,-964.57)
S1_16.S10_N: P4.46 U16.P1 | length 762.1
  Top Layer w5: U16.P1@98.43,-413.39 cw(c98.43,-428.77) 113.81,-428.77 113.81,-452.76 113.81,-585.78 ccw(c300.81,-585.78) 300.81,-772.78 414.93,-772.78 cw(c414.93,-842.52) 484.66,-842.52 484.66,-852.56 cw(c477.26,-852.56) 482.5,-857.8 cw(c479.95,-855.26) 479.95,-858.85 ccw(c479.95,-862.45) 477.42,-859.9 475.84,-861.48 ccw(c482.18,-867.81) 473.21,-867.81 P4.46@473.21,-900.6
S1_16.S10_P: P4.48 U16.R1 | length 762.1
  Top Layer w5: U16.R1@137.8,-413.39 ccw(c137.8,-428.77) 122.41,-428.77 122.41,-452.76 122.41,-585.78 ccw(c300.81,-585.78) 300.81,-764.18 414.93,-764.18 cw(c414.93,-842.52) 493.26,-842.52 493.26,-852.56 ccw(c500.67,-852.56) 495.43,-857.8 ccw(c497.98,-855.26) 497.98,-858.85 cw(c497.98,-862.45) 500.51,-859.9 502.1,-861.48 cw(c495.75,-867.81) 504.71,-867.81 P4.48@504.71,-900.6
S1_16.S11_N: P4.52 U16.U1 | length 791.7
  Top Layer w5: U16.U1@216.54,-413.39 ccw(c216.54,-428.77) 201.15,-428.77 201.15,-452.76 201.15,-592.07 ccw(c295.28,-592.07) 295.28,-686.2 499.11,-686.2 cw(c499.11,-743.35) 556.26,-743.35 556.26,-852.56 ccw(c563.67,-852.56) 558.43,-857.8 ccw(c560.98,-855.26) 560.98,-858.85 cw(c560.98,-862.45) 563.51,-859.9 565.1,-861.48 cw(c558.75,-867.81) 567.71,-867.81 P4.52@567.71,-900.6
S1_16.S11_P: P4.50 U16.T1 | length 791.7
  Top Layer w5: U16.T1@177.17,-413.39 cw(c177.17,-428.77) 192.55,-428.77 192.55,-452.76 192.55,-592.07 ccw(c295.28,-592.07) 295.28,-694.8 499.11,-694.8 cw(c499.11,-743.35) 547.66,-743.35 547.66,-852.56 cw(c540.26,-852.56) 545.5,-857.8 cw(c542.95,-855.26) 542.95,-858.85 ccw(c542.95,-862.45) 540.42,-859.9 538.84,-861.48 ccw(c545.18,-867.81) 536.21,-867.81 P4.50@536.21,-900.6
S1_16.S12_N: P4.54 U16.N5 | length 1213.8
  Top Layer w5: U16.N5@59.06,-255.91 v1(78.74,-275.59) ; P4.54@599.2,-900.6 599.2,-933.39 ccw(c608.16,-933.39) 601.82,-939.72 603.4,-941.3 ccw(c605.94,-938.76) 605.94,-942.35 cw(c605.94,-945.95) 608.48,-943.41 cw(c603.24,-948.64) 610.65,-948.64 610.65,-949 cw(c598.36,-949) 607.05,-957.69 605.76,-958.98 ccw(c611.35,-964.57) v2(603.45,-964.57)
  Int2 (Sign) w3: v1(78.74,-275.59) 78.74,-255.9 cw(c82.68,-255.9) 82.68,-251.97 cw(c82.68,-261.47) 89.4,-254.75 90.55,-255.91 ccw(c100.06,-246.4) 100.06,-259.84 cw(c100.06,-262.84) 100.14,-259.84 102.99,-259.9 105.93,-259.96 ccw(c106.3,-242.46) 106.3,-259.97 ; 102.99,-259.97 106.3,-259.97 ; v2(603.45,-964.57) cw(c610.11,-964.57) 605.4,-959.86 ccw(c592,-946.46) 610.95,-946.46 ccw(c580.34,-946.46) 601.98,-924.82 556.85,-879.68 ccw(c486.14,-950.39) 486.14,-850.39 358.27,-850.39 cw(c358.27,-744.09) 251.97,-744.09 251.97,-522.07 ccw(c206.99,-522.07) 238.8,-490.27 234.47,-485.94 cw(c287.26,-433.15) 212.6,-433.15 212.6,-315.09 ccw(c196.85,-315.09) 196.85,-299.34 cw(c196.85,-275.72) 173.23,-275.72 ccw(c157.48,-275.72) 157.48,-259.97 106.3,-259.97
S1_16.S12_P: P4.56 U16.P6 | length 1215.4
  Top Layer w5: U16.P6@98.43,-216.54 v1(118.11,-236.22) ; v2(626.45,-964.57) ccw(c618.55,-964.57) 624.14,-958.99 622.85,-957.69 cw(c631.54,-949) 619.25,-949 619.25,-948.64 cw(c626.65,-948.64) 621.42,-943.41 cw(c623.96,-945.95) 623.96,-942.35 ccw(c623.96,-938.76) 626.49,-941.31 628.07,-939.73 ccw(c621.74,-933.39) 630.7,-933.39 P4.56@630.7,-900.6
  Int2 (Sign) w3: v1(118.11,-236.22) 98.42,-236.22 ccw(c98.42,-240.16) 94.49,-240.16 ccw(c103.99,-240.16) 97.27,-246.88 99.58,-249.18 ccw(c106.3,-242.46) 106.3,-251.97 157.48,-251.97 cw(c157.48,-275.72) 181.23,-275.72 ccw(c196.85,-275.72) 196.85,-291.34 cw(c196.85,-315.09) 220.6,-315.09 220.6,-433.07 ccw(c287.44,-433.07) 240.17,-480.33 244.48,-484.64 cw(c207.09,-522.03) 259.97,-522.03 259.97,-744.09 ccw(c358.27,-744.09) 358.27,-842.39 486.27,-842.39 cw(c486.27,-950.06) 562.41,-873.93 607.7,-919.22 cw(c580.54,-946.38) 618.95,-946.38 618.95,-946.46 ccw(c637.9,-946.46) 624.5,-959.86 cw(c619.79,-964.57) v2(626.45,-964.57)
S1_16.S13_N: P4.60 U16.V2 | length 893.6
  Top Layer w5: U16.V2@255.91,-374.02 ccw(c255.91,-389.7) 240.22,-389.7 240.22,-452.76 240.22,-559.12 ccw(c275.59,-559.12) 275.59,-594.49 509.17,-594.49 cw(c509.17,-767.52) 682.2,-767.52 682.2,-852.59 ccw(c689.54,-852.59) 684.35,-857.78 ccw(c686.93,-855.2) 686.93,-858.85 cw(c686.93,-862.51) 689.52,-859.92 691.08,-861.48 cw(c684.74,-867.81) 693.7,-867.81 P4.60@693.7,-900.6
S1_16.S13_P: P4.58 U16.U2 | length 894.1
  Top Layer w5: U16.U2@216.54,-374.02 cw(c216.54,-389.7) 232.22,-389.7 232.22,-433.07 231.72,-433.07 231.72,-452.76 231.72,-559.12 ccw(c275.59,-559.12) 275.59,-602.99 509.17,-602.99 cw(c509.17,-767.52) 673.7,-767.52 673.7,-852.59 cw(c666.35,-852.59) 671.55,-857.78 cw(c668.96,-855.2) 668.96,-858.85 ccw(c668.96,-862.51) 666.38,-859.92 664.82,-861.48 ccw(c671.16,-867.81) 662.2,-867.81 P4.58@662.2,-900.6
S1_16.S14_N: P4.62 U16.H15 | length 1879
  Top Layer w5: v1(-157.48,157.48) U16.H15@-137.8,137.8 ; P4.62@725.18,-900.6 725.18,-933.39 ccw(c734.14,-933.39) 727.8,-939.72 729.38,-941.3 ccw(c731.92,-938.76) 731.92,-942.35 cw(c731.92,-945.95) 734.46,-943.41 cw(c729.23,-948.64) 736.63,-948.64 736.63,-949 cw(c724.34,-949) 733.03,-957.69 731.75,-958.98 ccw(c737.33,-964.57) v2(729.43,-964.57)
  Int2 (Sign) w3: v1(-157.48,157.48) cw(c-157.48,141.86) -141.86,141.86 -141.86,-39.37 ccw(c-118.24,-39.37) -118.24,-62.99 236.22,-62.99 cw(c236.22,-78.61) 251.84,-78.61 251.84,-157.48 ccw(c275.59,-157.48) 275.59,-181.23 314.96,-181.23 cw(c314.96,-196.98) 330.71,-196.98 330.71,-354.46 ccw(c354.33,-354.46) 354.33,-378.08 433.07,-378.08 cw(c433.07,-393.7) 448.69,-393.7 448.69,-393.78 ccw(c552.76,-393.78) 479.17,-467.36 550.08,-538.27 cw(c509.71,-578.64) 566.8,-578.64 566.8,-679.09 ccw(c599.88,-679.09) 576.44,-702.43 ccw(c599.88,-679.09) 576.49,-702.48 707.64,-833.63 cw(c636.93,-904.34) 736.93,-904.34 736.93,-946.46 cw(c717.98,-946.46) 731.38,-959.86 ccw(c736.09,-964.57) v2(729.43,-964.57)
S1_16.S14_P: P4.64 U16.J15 | length 1874.1
  Top Layer w5: v1(-118.11,157.48) U16.J15@-98.43,137.8 ; v2@750.48,-959.86 750.48,-959.35 747.86,-956.72 cw(c754.19,-950.38) 745.23,-950.38 745.23,-948.64 cw(c752.64,-948.64) 747.4,-943.41 cw(c749.94,-945.95) 749.94,-942.35 ccw(c749.94,-938.76) 752.48,-941.31 754.06,-939.73 ccw(c747.72,-933.39) 756.68,-933.39 P4.64@756.68,-900.6
  Int2 (Sign) w3: v1(-118.11,157.48) ccw(c-118.11,141.73) -133.86,141.73 -133.86,-39.37 ccw(c-118.24,-39.37) -118.24,-54.99 236.22,-54.99 cw(c236.22,-78.61) 259.84,-78.61 259.84,-157.48 ccw(c275.59,-157.48) 275.59,-173.23 314.96,-173.23 cw(c314.96,-196.98) 338.71,-196.98 338.71,-354.46 ccw(c354.33,-354.46) 354.33,-370.08 433.07,-370.08 cw(c433.07,-393.7) 456.69,-393.7 ccw(c552.94,-393.7) 484.88,-461.76 555.76,-532.64 cw(c509.79,-578.61) 574.8,-578.61 574.8,-679.02 ccw(c600.04,-679.02) 582.19,-696.86 713.37,-828.04 cw(c637.17,-904.24) 744.93,-904.24 744.93,-946.46 ccw(c763.88,-946.46) 750.48,-959.86 cw(c745.77,-964.57) v2(752.43,-964.57)
S1_16.S15_N: P4.68 U16.Y1 | length 838.2
  Top Layer w5: U16.Y1@334.65,-413.39 ccw(c334.65,-429.07) 318.96,-429.07 318.96,-437.55 ccw(c328.15,-437.55) 321.65,-444.05 324.34,-446.75 324.7,-446.75 330.71,-452.76 365.5,-487.55 ccw(c436.21,-416.84) 436.21,-516.84 619.71,-516.84 cw(c619.71,-573.14) 659.52,-533.33 776.52,-650.32 cw(c700.07,-726.77) 808.18,-726.77 808.18,-852.59 ccw(c815.53,-852.59) 810.33,-857.78 ccw(c812.92,-855.2) 812.92,-858.85 cw(c812.92,-862.51) 815.5,-859.92 817.06,-861.48 cw(c810.72,-867.81) 819.68,-867.81 P4.68@819.68,-900.6
S1_16.S15_P: P4.66 U16.W1 | length 837.9
  Top Layer w5: U16.W1@295.28,-413.39 cw(c295.28,-429.07) 310.96,-429.07 310.96,-439.21 ccw(c324.15,-439.21) 314.82,-448.54 318.69,-452.4 318.69,-452.76 359.52,-493.59 ccw(c436.17,-416.94) 436.17,-525.34 619.67,-525.34 cw(c619.67,-573.24) 653.54,-539.37 770.39,-656.22 cw(c699.68,-726.93) 799.68,-726.93 799.68,-852.59 cw(c792.34,-852.59) 797.53,-857.78 cw(c794.95,-855.2) 794.95,-858.85 ccw(c794.95,-862.51) 792.36,-859.92 790.81,-861.48 ccw(c797.14,-867.81) 788.18,-867.81 P4.66@788.18,-900.6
